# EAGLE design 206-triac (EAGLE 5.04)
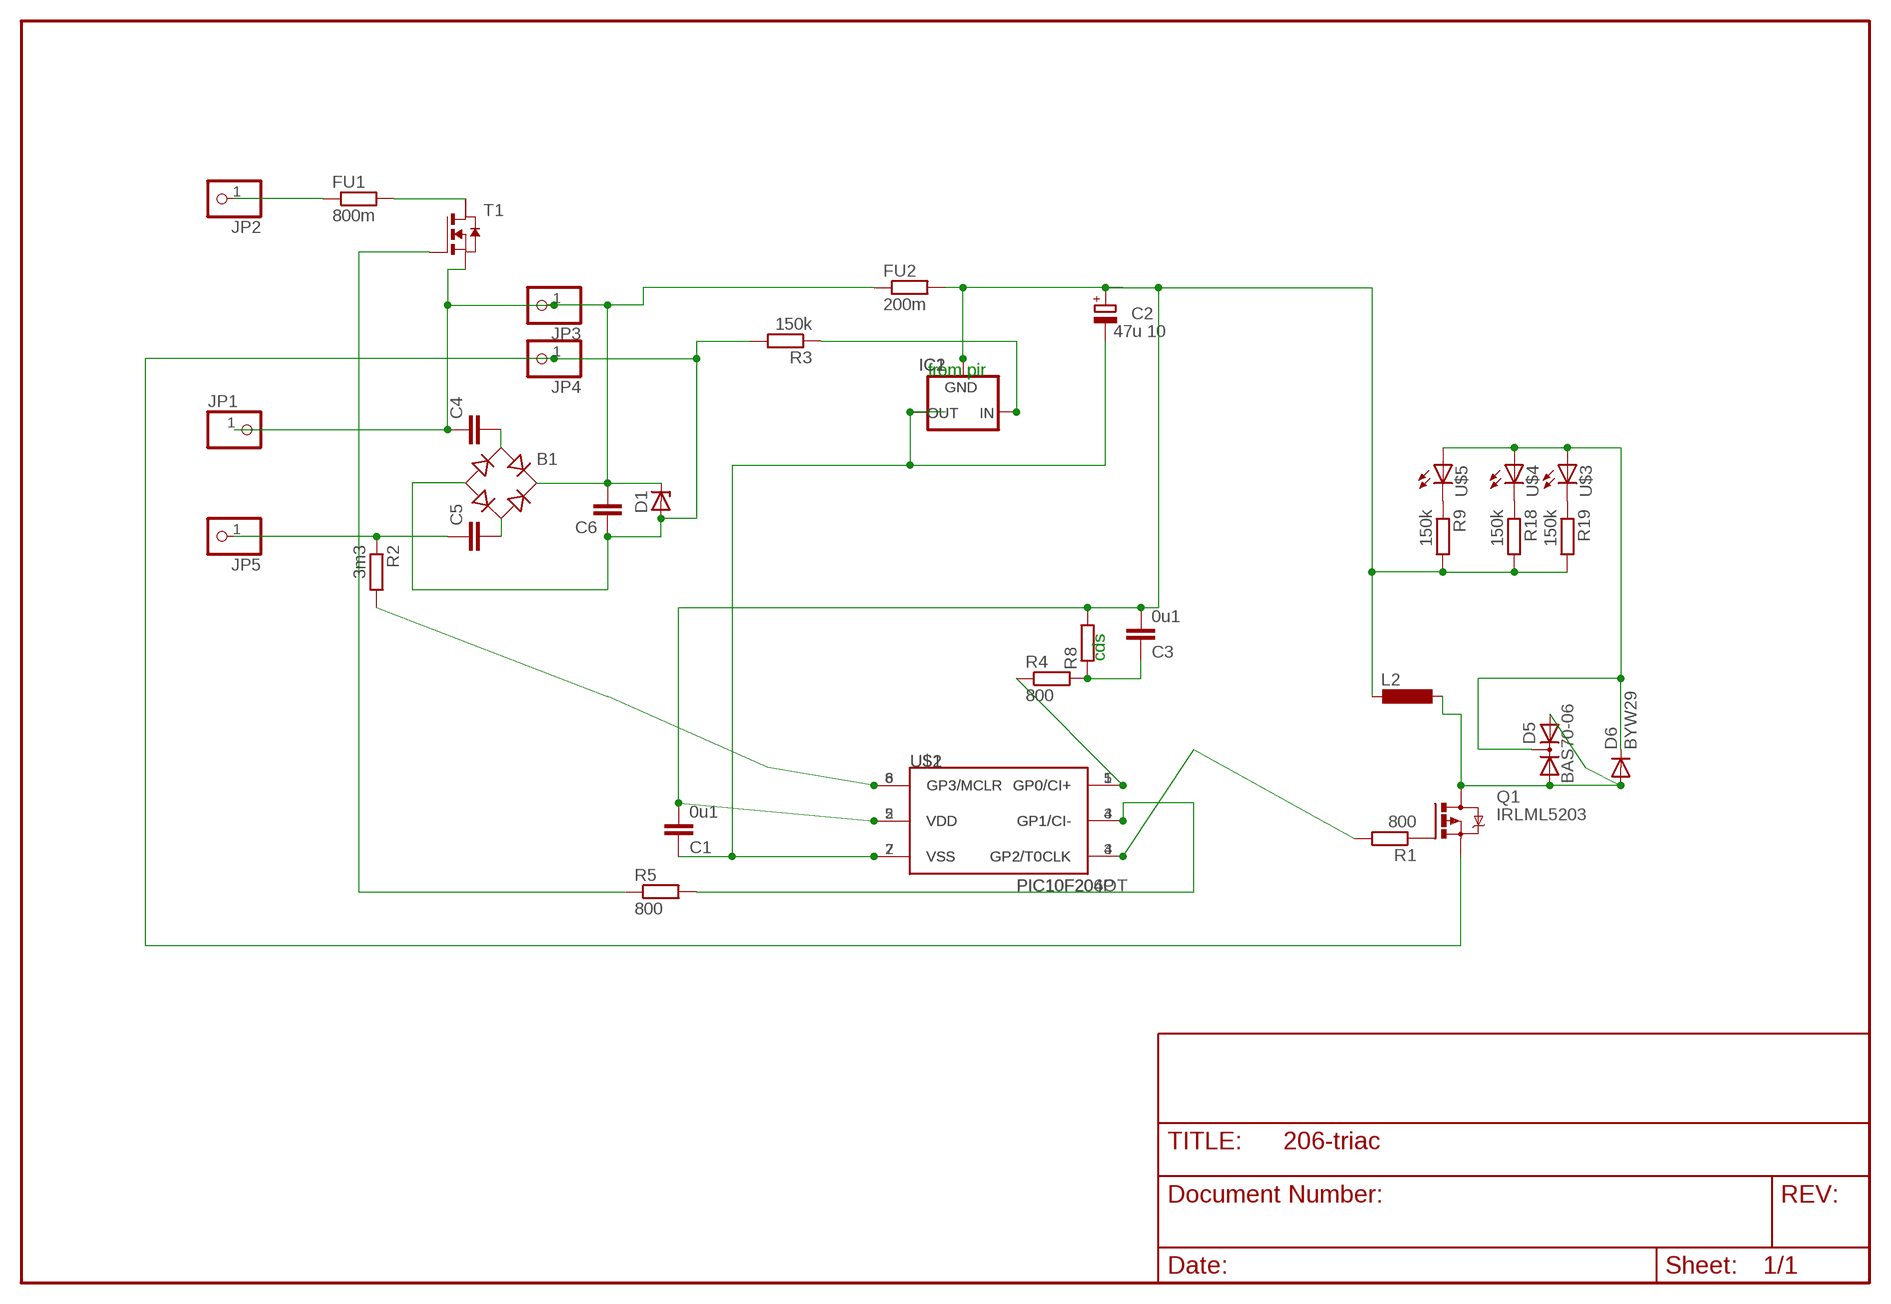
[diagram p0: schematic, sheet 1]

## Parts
B1  RB1A  [RB1A]
C1  0u1  C-EUC1206  [C1206]
C2  47u 10  CPOL-EUE2.5-5  [E2,5-5]
C3  0u1  C-EUC1206  [C1206]
C4  C-EU050-025X075  [C050-025X075]
C5  C-EU050-025X075  [C050-025X075]
C6  C-EU050-025X075  [C050-025X075]
D1  ZENER-DIODESOT23  [SOT23]
D5  BAS70-06  [SOT23]
D6  BYW29  [DO220S]
FU1  800m  R-EU_0204/5  [0204/5]
FU2  200m  R-EU_0204/5  [0204/5]
IC1  XC63FPT  [TO92]
IC2  XC63FPP  [SOT89R]
JP1  PINHD-1X1  [1X01]
JP2  PINHD-1X1  [1X01]
JP3  PINHD-1X1  [1X01]
JP4  PINHD-1X1  [1X01]
JP5  PINHD-1X1  [1X01]
L2  L-EU0207/7  [0207/7]
Q1  IRLML5203  [MICRO3]
R1  800  R-EU_R1206  [R1206]
R2  3m3  R-EU_R1206  [R1206]
R3  150k  R-EU_R1206  [R1206]
R4  800  R-EU_R1206  [R1206]
R5  800  R-EU_R1206  [R1206]
R8  R-EU_0207/5V  [0207/5V]
R9  150k  R-EU_R1206  [R1206]
R18  150k  R-EU_R1206  [R1206]
R19  150k  R-EU_R1206  [R1206]
T1  NMOSSOT223  [SOT223]
U$1  PIC10F206P  [DIL8]
U$2  PIC10F204OT  [SOT23-6]
U$3  LED5MM  [LED5MM]
U$4  LED5MM  [LED5MM]
U$5  LED5MM  [LED5MM]

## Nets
N$1: B1.+ C4.1 C6.2 D1.3(C) FU2.1 JP1.1 JP3.1 T1.3(S)
N$4: FU1.1 JP2.1
N$6: C1.1 C2.- IC1.3(OUT) IC2.3(OUT) U$1.7(VSS) U$2.2(VSS)
N$7: D5.3(C) D6.C U$3.A U$4.A U$5.A
N$8: B1.- C6.1 D1.1(A) JP4.1 Q1.2(S) R3.2
N$9: FU1.2 T1.2(D)
N$10: Q1.1(G) R1.1
N$11: R5.1 T1.1(G)
N$12: R2.2 U$1.8(GP3/MCLR) U$2.6(GP3/MCLR)
N$13: R5.2 U$1.4(GP1/CI-) U$2.3(GP1/CI-)
N$14: R1.2 U$1.3(GP2/T0CLK) U$2.4(GP2/T0CLK)
N$15: IC1.2(IN) IC2.2(IN) R3.1
N$23: C3.1 R4.2 R8.1
N$26: D5.1(A1) D5.2(A2) D6.A L2.1 Q1.3(D)
N$29: R4.1 U$1.5(GP0/CI+) U$2.1(GP0/CI+)
N$32: B1.AC2 C5.2
N$33: B1.AC1 C4.2
N$37: C5.1 JP5.1 R2.1
N$38: R9.1 U$5.K(C)
N$54: R18.1 U$4.K(C)
N$55: R19.1 U$3.K(C)
V2CC: C1.2 C2.+ C3.2 FU2.2 IC1.1(GND) IC2.1(GND) L2.2 R8.2 R9.2 R18.2 R19.2 U$1.2(VDD) U$2.5(VDD)
Unconnected: T1.4(D2)

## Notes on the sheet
- from pir
- cds

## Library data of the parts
B1 = rectifier:RB1A: RECTIFIER 1 A
C1 C3-C6 = rcl:C-EU: CAPACITOR, European symbol
C2 = rcl:CPOL-EU: POLARIZED CAPACITOR, European symbol
D1 = diode-1:ZENER-DIODE: Z-Diode
D5 = diode-1:BAS70-06: Silicon Schottky Diodes General-purpose diode for high-speed switching
D6 = diode:BYW29: DIODE
FU1 FU2 R1-R5 R9 R18 R19 = rcl:R-EU_: RESISTOR, European symbol
IC1 IC2 = v-reg:XC63FP: Positiv Voltage Regulators www.torex.co.jp/english/product/pro02/pdf/0201_xc62fp.pdf
JP1-JP5 = pinhead:PINHD-1X1: PIN HEADER
L2 = rcl:L-EU: INDUCTOR, European symbol
Q1 = transistor-power:IRLML5203: HEXFET P-Channel Power MOSFET
R8 = rcl(2):R-EU_: RESISTOR, European symbol
T1 = zetex:NMOSSOT223: MOS FET
U$1 U$2 = microchip-3:PIC10F2*: uPC nW 0,25/0,5k Program Flash memory Comparator
U$3-U$5 = led(3):LED: LED

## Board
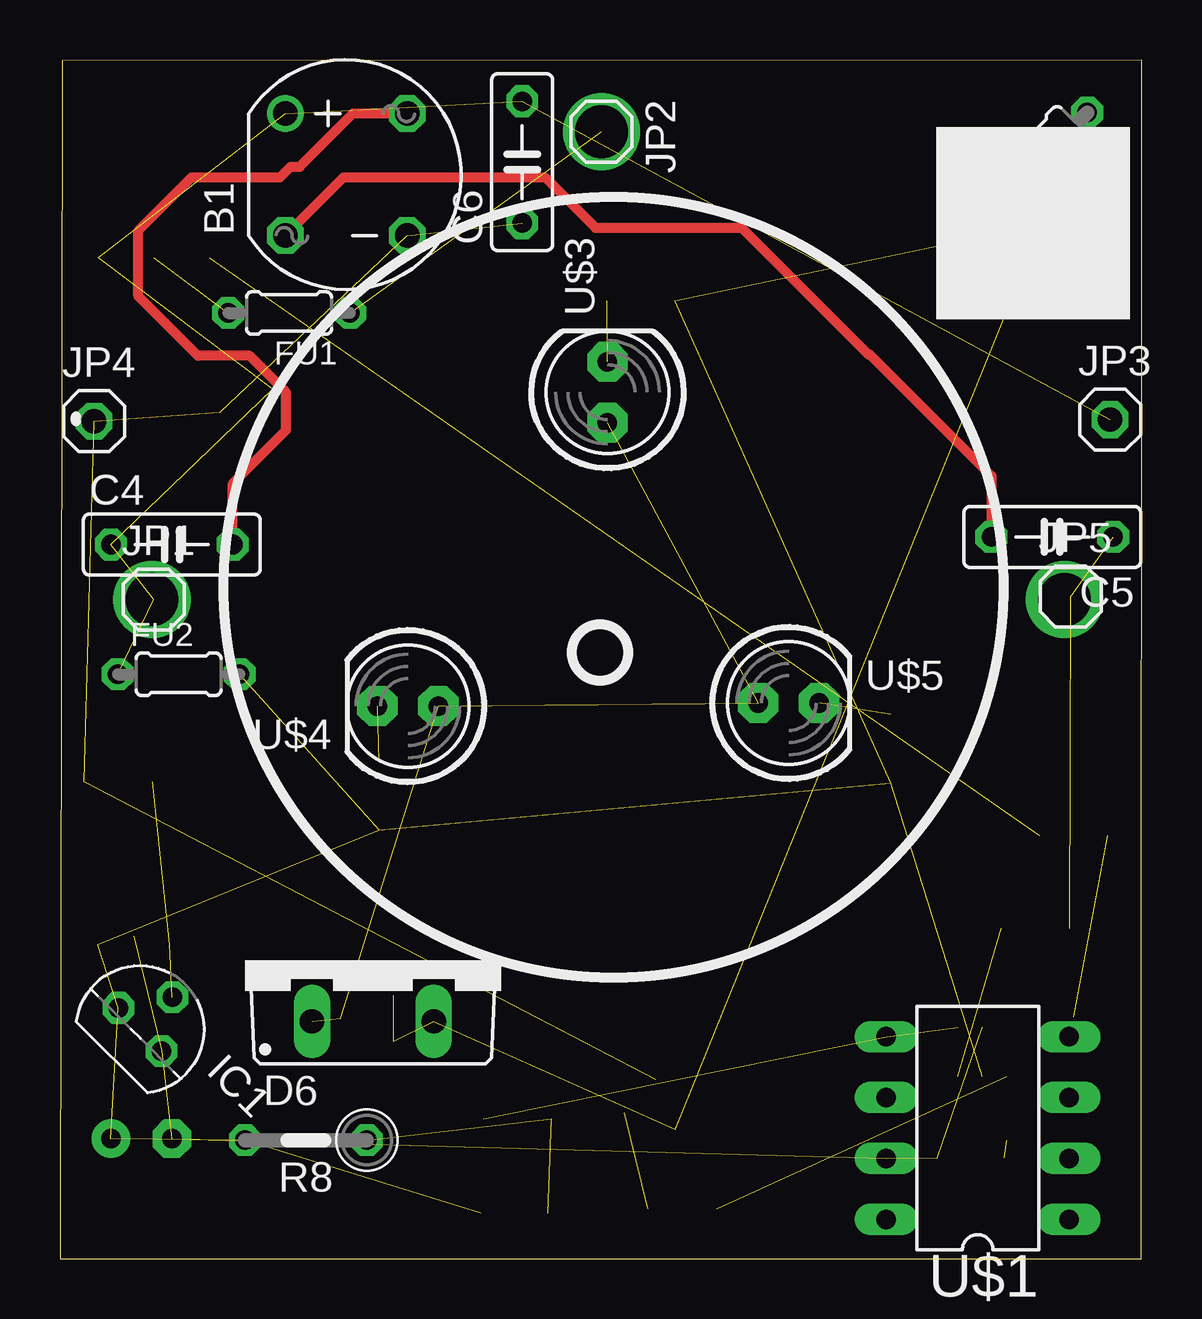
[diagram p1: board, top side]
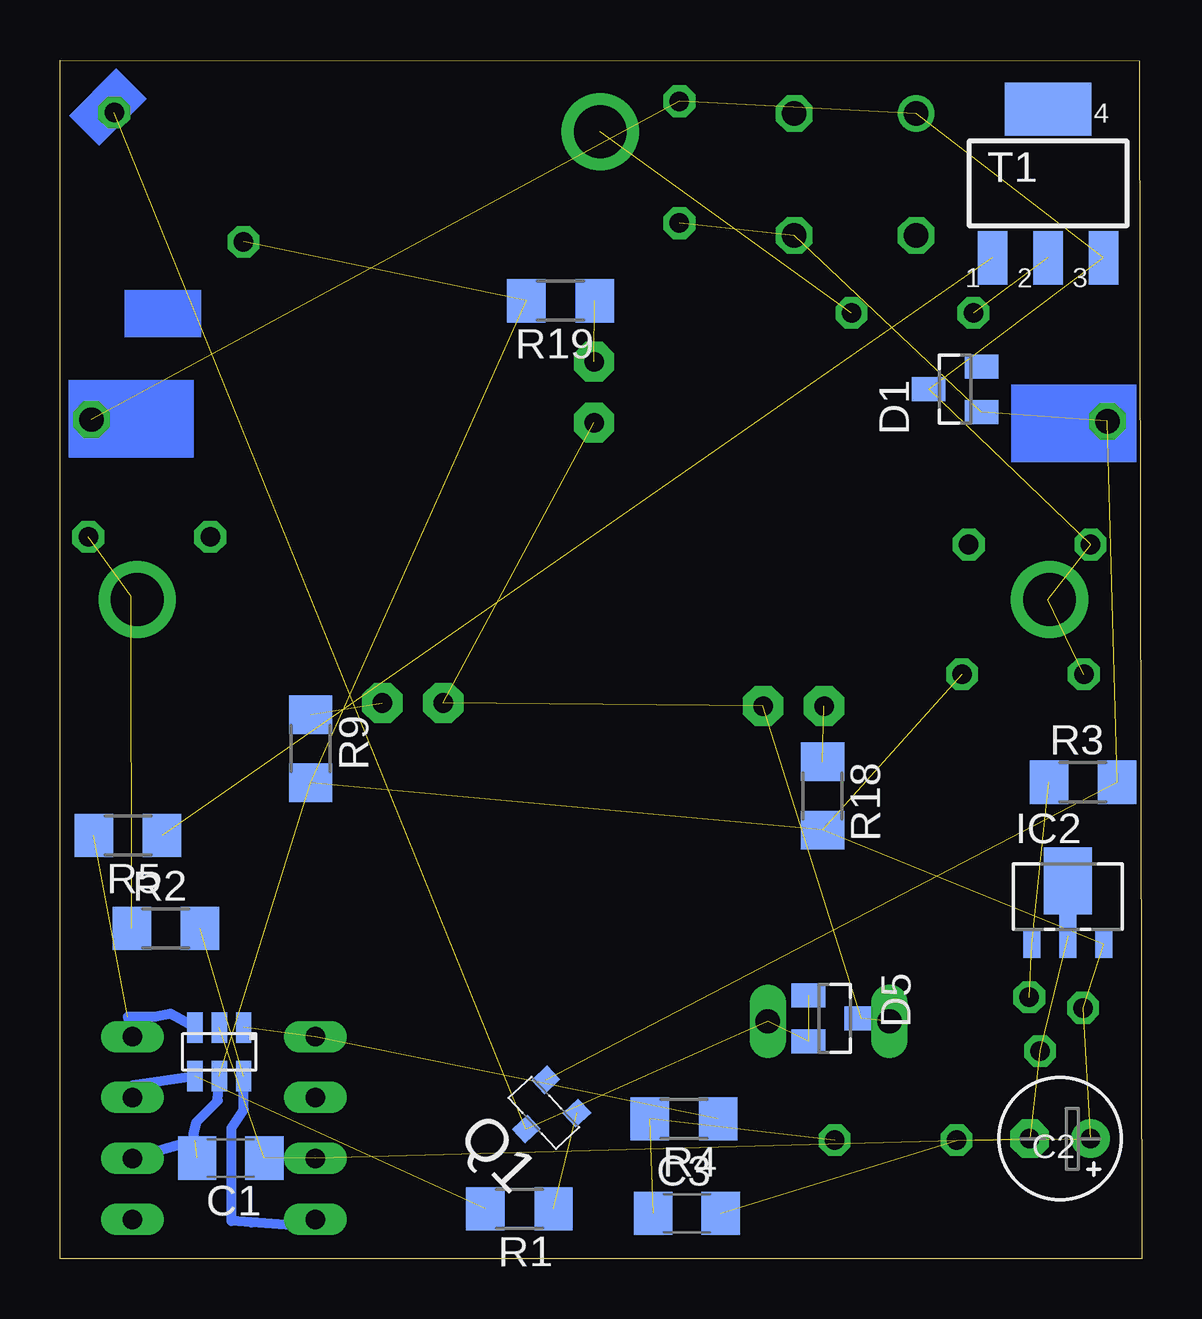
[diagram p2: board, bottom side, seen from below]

Size 45.09 x 49.97 mm. Coordinates in mm from the lower left corner, seen from the top.
Outline: 0,0 45.07,0 45.08,49.97 0.09,49.94 0,0
Copper layers (1*16): Top 0.035mm / dielectric 1.5mm / Bottom 0.035mm
Design rules "default": minimum track width 10mil, minimum drill 24mil, track to track 8mil, track to pad 8mil, pad to pad 8mil, via to via 8mil, smd to smd 8mil, copper to edge 40mil, drill to drill 8mil, minimum pad ring 10mil, minimum via ring 8mil, stop-mask expansion 4mil, vias tented up to drill 0mil, thermal gap 10mil

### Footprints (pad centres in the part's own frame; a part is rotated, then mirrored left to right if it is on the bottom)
RB1A = drill 1.016 round: + -2.54,2.54 | drill 1.016 octagon: - 2.54,-2.54; AC1 2.54,2.54; AC2 -2.54,-2.54
C1206 = smd 1.6 x 1.8: 1 -1.4,0; 2 1.4,0
E2,5-5 = drill 0.813 pad 1.6 round: + -1.27,0 | drill 0.813 pad 1.6 octagon: - 1.27,0
C050-025X075 = drill 0.813 octagon: 1 -2.54,0; 2 2.54,0
SOT23 = smd 1 x 1.4: 1 -0.95,-1.1; 2 0.95,-1.1; 3 0,1.1
DO220S = drill 1.016 long: A 2.54,-2.54; C -2.54,-2.54
0204/5 = drill 0.813 octagon: 1 -2.54,0; 2 2.54,0
TO92 = drill 0.813 octagon: 1 -1.27,0; 2 0,1.905; 3 1.27,0
SOT89R = smd 0.7 x 1.1: 1 1.5,-1.75; 2 -1.5,-1.75 | smd 0.7 x 1.8: 3 0,-1.4 | smd 2 x 2.8: 4 0,0.9
1X01 = drill 1.016 octagon: 1 0,0
0207/7 = drill 0.813 octagon: 1 -3.81,0; 2 3.81,0
MICRO3 = smd 0.8 x 0.9: 1 -0.95,-1; 2 0.95,-1; 3 0,1
R1206 = smd 1.6 x 1.803: 1 -1.422,0; 2 1.422,0
0207/5V = drill 0.813 octagon: 1 -2.54,0; 2 2.54,0
SOT223 = smd 1.219 x 2.235: 1 -2.311,-3.099; 2 0,-3.099; 3 2.311,-3.099 | smd 3.6 x 2.2: 4 0,3.099
DIL8 = drill 0.813 long: 1 -3.81,-3.81; 2 -1.27,-3.81; 3 1.27,-3.81; 4 3.81,-3.81; 5 3.81,3.81; 6 1.27,3.81; 7 -1.27,3.81; 8 -3.81,3.81
SOT23-6 = smd 0.635 x 1.27: 1 -1.016,-1.016; 2 0,-1.016; 3 1.016,-1.016; 4 1.016,1.016; 5 0,1.016; 6 -1.016,1.016
LED5MM = drill 0.813 pad 1.676 octagon: A -1.27,0; K 1.27,0

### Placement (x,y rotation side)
B1  11.93,45.2 0 top
C1  37.97,4.21 180 bottom
C2  3.39,5.01 180 bottom
C3  18.95,1.9 0 bottom
C4  4.66,29.78 0 top
C5  41.36,30.09 180 top
C6  19.27,45.71 90 top
D1  7.77,36.25 90 bottom
D5  12.79,10.03 270 bottom
D6  13.04,12.44 0 top
FU1  9.55,39.43 180 top
FU2  4.95,24.37 0 top
IC1  3.34,9.56 315 top
IC2  3.07,14.85 0 bottom
JP1  3.9,27.49 0 top
JP2  22.57,46.98 270 top
JP3  43.78,34.98 0 top
JP4  1.42,34.92 0 top
JP5  42.13,27.62 0 top
L2  40.13,45.09 225 top
Q1  24.92,6.09 133.1 bottom
R1  25.93,2.09 180 bottom
R2  40.67,13.77 0 bottom
R3  2.44,19.87 0 bottom
R4  19.08,5.84 180 bottom
R5  42.25,17.65 180 bottom
R8  10.25,4.95 180 top
R9  34.63,21.27 270 bottom
R18  13.3,19.3 270 bottom
R19  24.22,39.94 180 bottom
T1  3.9,44.83 0 bottom
U$1  38.25,5.46 90 top
U$2  38.44,8.63 180 bottom
U$3  22.82,36.13 90 top
U$4  14.5,23.05 180 top
U$5  30.38,23.17 0 top

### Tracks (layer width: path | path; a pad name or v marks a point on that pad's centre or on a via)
N$1  (7 unrouted)
N$2  (via drill 2.2)
  other vias: 3.84,27.49
N$3  (via drill 2.2)
  other vias: 41.87,27.49
N$4  (1 unrouted)
N$5  (via drill 2.2)
  other vias: 22.57,46.98
N$6  (5 unrouted)
N$7  (4 unrouted)
N$8  (5 unrouted)
N$9  (1 unrouted)
N$10  (1 unrouted)
N$11  (1 unrouted)
N$12  (1 unrouted)
  Bottom 0.406: U$1.8 35.4,1.39 37.11,1.52 37.94,1.58 37.94,5.46 37.43,6.22 U$2.6
N$13  (1 unrouted)
  Bottom 0.406: U$2.3 40.48,10.22 41.11,10.09 42.25,10.09 U$1.4
N$14  (1 unrouted)
  Bottom 0.406: U$2.4 42.06,7.23 U$1.3
N$15  (2 unrouted)
N$23  (2 unrouted)
N$26  (4 unrouted)
N$29  (2 unrouted)
N$32
  Top 0.406: C5.2 38.82,32.63 33.74,37.71 33.68,37.71 28.41,42.98 22.31,42.98 20.22,45.08 11.81,45.08 B1.AC2
N$33
  Top 0.406: C4.2 7.2,32.32 9.42,34.54 9.42,36.13 7.9,37.65 5.74,37.65 3.26,40.13 3.26,42.86 5.49,45.08 9.17,45.08 9.61,45.52 10,45.52 12.22,47.75 14.47,47.75 B1.AC1
N$37  (2 unrouted)
N$38  (1 unrouted)
N$54  (1 unrouted)
N$55  (1 unrouted)
V2CC  (11 unrouted)
  Bottom 0.406: U$1.2 39.46,4.95 39.52,5.2 39.4,5.71 38.51,6.6 U$2.5
(copper drawn outside any net)
  shapes: Bottom area x4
